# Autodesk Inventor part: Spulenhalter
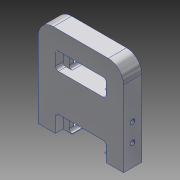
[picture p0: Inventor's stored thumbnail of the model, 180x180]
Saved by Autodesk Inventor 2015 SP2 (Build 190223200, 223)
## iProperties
Created: 2012-07
Part Number: Spulenhalter
Material: Aluminium 6061
Document SubType Name: Modeling
Designer: rYan
Density: 2.71 g/cm^3
Mass: 9.07491 g
Surface Area: 21.2088 cm^2
Volume: 3.34868 cm^3
Appearance: Aluminium - flach
Author: rYan
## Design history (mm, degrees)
sketch "Skizze8"
  geometry: L1 (0, -6)-(0, 36) reference; L2 (-19.6, 0)-(19.6, 0) reference; L3 (-14, 0)-(-14, 30); L4 (-14, 30)-(14, 30); L5 (14, 30)-(14, 0); L6 (6.35, 5.9)-(-6.35, 5.9); L7 (-6.35, 5.9)-(-6.35, 0.2); L8 (6.35, 0.2)-(6.35, 5.9); L9 (6.35, 23.85)-(-6.35, 23.85); L10 (-6.35, 23.85)-(-6.35, 18.15); L11 (-6.35, 18.15)-(6.35, 18.15); L12 (6.35, 18.15)-(6.35, 23.85); L13 (14, 0)-(5.35, 0); L14 (-6.35, 21)-(6.35, 21); L15 (5.35, 0)-(5.35, 0.2); L16 (5.35, 0.2)-(6.35, 0.2); L17 (-6.35, 0.2)-(-5.35, 0.2); L18 (-5.35, 0.2)-(-5.35, 0); L19 (-14, 0)-(-5.35, 0); 1 further point
  constraints: 34 end point, 7 point on line, 5 parallel, 5 perpendicular, 3 horizontal, 2 midpoint, 1 collinear, 1 vertical, 5 other
  dimensions: "d55" = 12.7 distance of L6.start L6.end; "d56" = 5.7 distance of L8.start L6.start; "d57" = 5.7 distance of L11.end L9.start; "d60" = 28 distance of L3.end L4.end; "d62" = 30 distance between parallel lines of L2 L4; "d133" = 21 distance between parallel lines of L14 L2; "d139" = 0.2 distance of L13.end L15.end; "d140" = 1 distance of L15.end L8.start
extrude "Extrusion4" new body sketch "Skizze8" distance "d63" = 6; taper "d64" = 0 deg
sketch "Skizze19"
  geometry: L1 (6.35, 18.15)-(-6.35, 18.15) reference; L2 (-6.35, 23.85)-(6.35, 23.85) reference; L3 (-6.35, 18.15)-(-6.35, 23.85) reference; L4 (6.35, 23.85)-(6.35, 18.15) reference; L5 (6.35, 5.9)-(-6.35, 5.9) reference; L6 (6.35, 0.2)-(6.35, 5.9) reference; L7 (-6.35, 5.9)-(-6.35, 0.2) reference; L8 (-8.35, 23.85)-(8.35, 23.85); L9 (8.35, 23.85)-(8.35, 18.15); L10 (8.35, 18.15)-(-8.35, 18.15); L11 (-8.35, 18.15)-(-8.35, 23.85); L12 (-8.35, 5.9)-(8.35, 5.9); L13 (8.35, 5.9)-(8.35, 0); L14 (8.35, 0)-(-8.35, 0); L15 (-8.35, 0)-(-8.35, 5.9); L16 (0, 36)-(0, -6) reference; L17 (-19.6, 0)-(19.6, 0) reference; 1 further point
  constraints: 16 end point, 4 parallel, 3 collinear, 3 point on line, 2 horizontal, 2 perpendicular, 1 other
  dimensions: "d146" = 2 distance between parallel lines of L3 L11
extrude "Extrusion8" cut sketch "Skizze19" distance "d147" = 2.5; taper "d148" = 0 deg
fillet "Rundung6" dims "d135" = 1
sketch "Skizze11"
  geometry: L1 (-11, 2.5)-(11, 2.5); L2 (0, 3)-(0, -0.5) reference; L3 (-7.35, 0)-(7.35, 0) reference; L4 (7.35, 0)-(-7.35, 0) reference; L5 (-7.35, 0)-(7.35, 0) reference; L6 (-14, 0)-(14, 0) reference; L7 (-8.35, 0)-(-14, 0) reference; L8 (14, 0)-(8.35, 0) reference; L9 (-7.35, 0)-(-8.35, 0) reference; L10 (8.35, 0)-(7.35, 0) reference; L11 (-8.35, 0)-(-7.35, 0) reference; L12 (-7.35, 0)-(-8.35, 0) reference; L13 (8.35, 0)-(7.35, 0) reference; L14 (7.35, 0)-(8.35, 0) reference; 4 further points
  constraints: 2 coincident, 2 end point, 1 horizontal, 1 point on line, 1 symmetric about line
  dimensions: "d88" = 11 distance from line of point (-11, 2.5) L2; "d125" = 2.5 distance between parallel lines of L1 L3
hole "Bohrung5" sketch "Skizze11" at (-11, 2.5), (11, 2.5) diameter "d79" = 3.242; stored, may be unused: countersink angle "d83" = 90 deg, drill point angle "d85" = 118 deg; dims "d80" = 8, "d81" = 5.6, "d82" = 3, "d84" = 5
fillet "Rundung2" dims "d89" = 5
sketch "Skizze15"
  geometry: L1 (-25, 0)-(-25, 6) reference; L2 (0, 0)-(0, 6) reference; L3 (-25, 3)-(0, 3); 2 further points
  constraints: 2 end point, 2 midpoint, 2 point on line
  dimensions: "d115" = 7 distance from line of point (-7, 3) L2; "d116" = 13 distance from line of point (-13, 3) L2
hole "Bohrung8" sketch "Skizze15" at (-13, 3), (-7, 3) diameter "d117" = 1.567; stored, may be unused: countersink angle "d121" = 90 deg, drill point angle "d123" = 118 deg; dims "d118" = 4, "d119" = 4, "d120" = 2, "d122" = 6
mirror "Spiegeln3"
sketch "Skizze16"
  geometry: L1 (-6.35, -18.15)-(6.35, -18.15) reference; L2 (6.35, -18.15)-(6.35, -23.85) reference; L3 (6.35, -23.85)-(-6.35, -23.85) reference; L4 (-6.35, -23.85)-(-6.35, -18.15) reference; L5 (6.35, -21)-(-6.35, -21); L6 (0, -23.85)-(0, -18.15); L7 (-8.5, -23)-(8.5, -23); L8 (8.5, -23)-(8.5, -19); L9 (8.5, -19)-(-8.5, -19); L10 (-8.5, -23)-(-8.5, -19); L11 (6.35, -0.2)-(6.35, -5.9) reference; L12 (-6.35, -5.9)-(-6.35, -0.2) reference; L13 (6.35, -5.9)-(-6.35, -5.9) reference; L14 (-8.5, -5)-(8.5, -5); L15 (8.5, -5)-(8.5, -1); L16 (8.5, -1)-(-8.5, -1); L17 (-8.5, -5)-(-8.5, -1); L18 (6.35, -3)-(-6.35, -3); L19 (0, -5.9)-(0, 0); 2 further points
  constraints: 26 end point, 5 midpoint, 4 point on line, 2 horizontal, 2 parallel, 2 perpendicular, 1 vertical, 4 other
  dimensions: "d127" = 4 distance of L7.end L8.end; "d132" = 4 distance of L14.end L15.end (= d127); "d134" = 2.9 distance between parallel lines of L13 L18; "d136" = 2.15 distance between parallel lines of L2 L8; "d137" = 2.15 distance between parallel lines of L11 L15
extrude "Extrusion7" cut sketch "Skizze16" distance "d128" = 2; taper "d129" = 0 deg
fillet "Rundung7" dims "d138" = 1
node "Volumenkörper2"
node "Projizierte Kontur8"
